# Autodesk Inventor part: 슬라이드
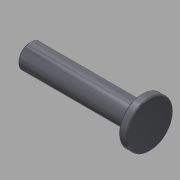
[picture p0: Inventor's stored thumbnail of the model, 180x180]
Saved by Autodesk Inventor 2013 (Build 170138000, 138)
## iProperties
Created: 2015-10
Part Number: 슬라이드
Document SubType Name: Modeling
Designer: mdu
Density: 7.86 g/cm^3
Material: 강철, 연강
Mass: 954.83 g
Surface Area: 210.251 cm^2
Volume: 121.48 cm^3
Author: mdu
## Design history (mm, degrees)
sketch "스케치1"
  geometry: L1 (-75, 162)-(-75, 58) reference; L2 (-148, 110)-(2, 110); L3 (-148, 110)-(-148, 125); L4 (-148, 125)-(-8, 125); L5 (-8, 125)-(-8, 139); L6 (-8, 139)-(2, 139); L7 (2, 139)-(2, 110); 2 further points
  constraints: 12 end point, 3 parallel, 3 perpendicular, 1 midpoint, 1 point on line
  dimensions: "d0" = 58 diameter of L6 L2; "d1" = 30 diameter of L4 L2; "d2" = 10 distance of L5.end L6.end; "d3" = 150 distance of L2.start L2.end; "d4" = 73 distance between parallel lines of L3 L1
revolve "회전1" sketch "스케치1" stored, may be unused: angle "d5" = 90 deg
hole "구멍1" diameter "d11" = 13.376; stored, may be unused: countersink angle "d15" = 90 deg, drill point angle "d17" = 118 deg; dims "d9" = 10, "d10" = 10, "d12" = 22, "d13" = 4, "d14" = 2, "d16" = 25
chamfer "모따기1" distance "d6" = 1; stored, may be unused: second distance "d7" = 2, angle "d8" = 45 deg
node "솔리드1"
node "참조1"
